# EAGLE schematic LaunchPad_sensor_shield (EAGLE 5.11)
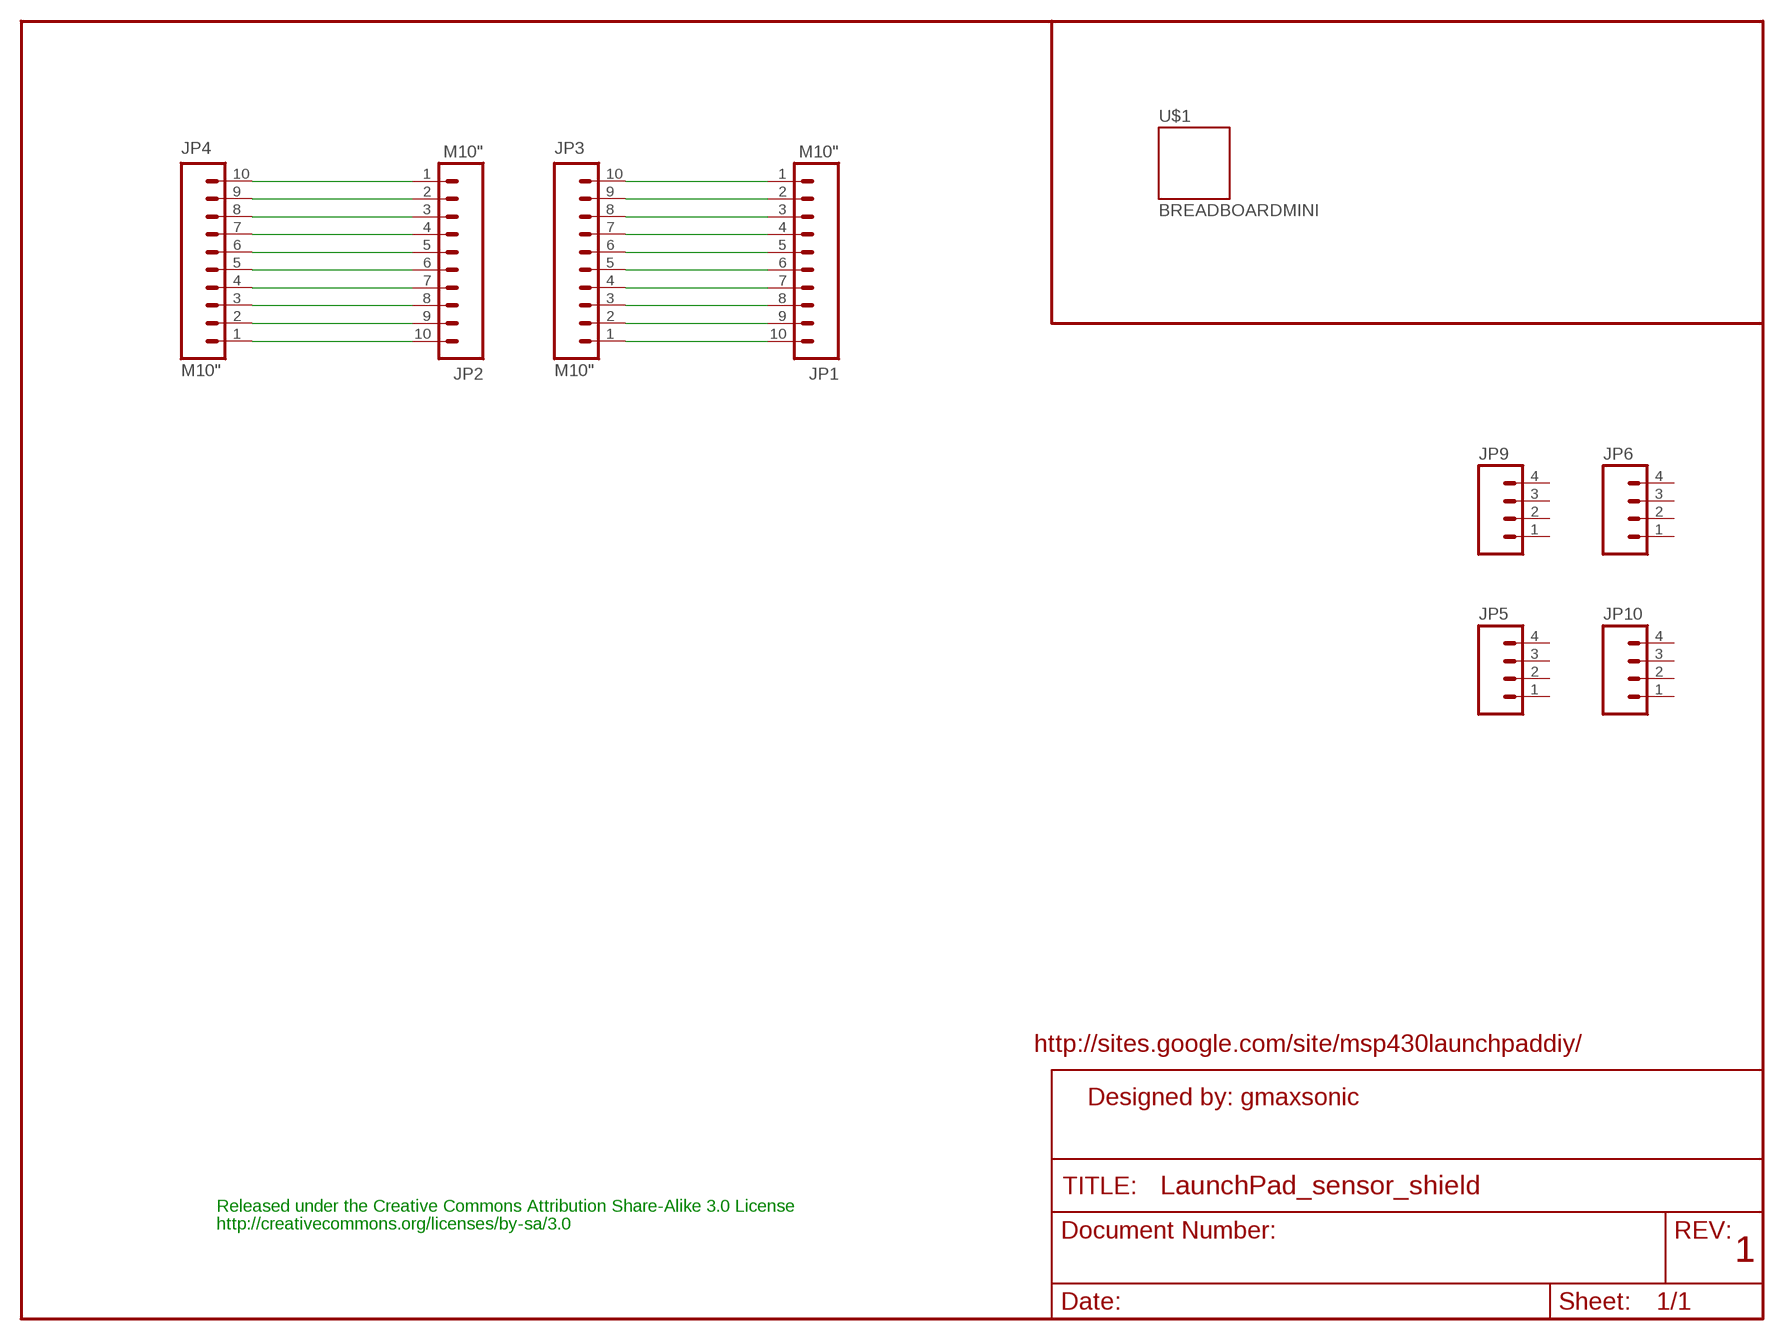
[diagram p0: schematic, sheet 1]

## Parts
JP1  M10"  [1X10]
JP2  M10"  [1X10]
JP3  M10"  [1X10]
JP4  M10"  [1X10]
JP5  M04PTH  [1X04]
JP6  M04PTH  [1X04]
JP9  M04PTH  [1X04]
JP10  M04PTH  [1X04]
U$1  BREADBOARDMINI  [BREADBOARD-MINI]

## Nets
N$1: JP2.1 JP4.10
N$2: JP2.2 JP4.9
N$3: JP2.3 JP4.8
N$4: JP2.4 JP4.7
N$5: JP2.5 JP4.6
N$6: JP2.6 JP4.5
N$7: JP2.7 JP4.4
N$8: JP2.8 JP4.3
N$9: JP2.9 JP4.2
N$10: JP2.10 JP4.1
N$11: JP1.1 JP3.10
N$12: JP1.2 JP3.9
N$13: JP1.3 JP3.8
N$14: JP1.4 JP3.7
N$15: JP1.5 JP3.6
N$16: JP1.6 JP3.5
N$17: JP1.7 JP3.4
N$18: JP1.8 JP3.3
N$19: JP1.9 JP3.2
N$20: JP1.10 JP3.1
Unconnected: JP5.1 JP5.2 JP5.3 JP5.4 JP6.1 JP6.2 JP6.3 JP6.4 JP9.1 JP9.2 JP9.3 JP9.4 JP10.1 JP10.2 JP10.3 JP10.4

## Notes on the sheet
- http://sites.google.com/site/msp430launchpaddiy/
- Designed by: gmaxsonic
- Released under the Creative Commons Attribution Share-Alike 3.0 License
- http://creativecommons.org/licenses/by-sa/3.0
- 1

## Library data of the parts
JP1-JP4 = SparkFun:M10: Header 10 Standard 10-pin 0.1" header. Use with straight break away headers (SKU : PRT-00116), right angle break away headers (PRT-00553), swiss pins (PRT-00743), machine pins (PRT-00117), and female headers (PRT-00115).
JP5 JP6 JP9 JP10 = SparkFun:M04: Header 4 Standard 4-pin 0.1" header. Use with straight break away headers (SKU : PRT-00116), right angle break away headers (PRT-00553), swiss pins (PRT-00743), machine pins (PRT-00117), and female headers (PRT-00115). Molex polarized connector foot print use with SKU : PRT-08231 with associated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
U$1 = SparkFun:BREADBOARD: Breadboard Mini Self Adhesive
